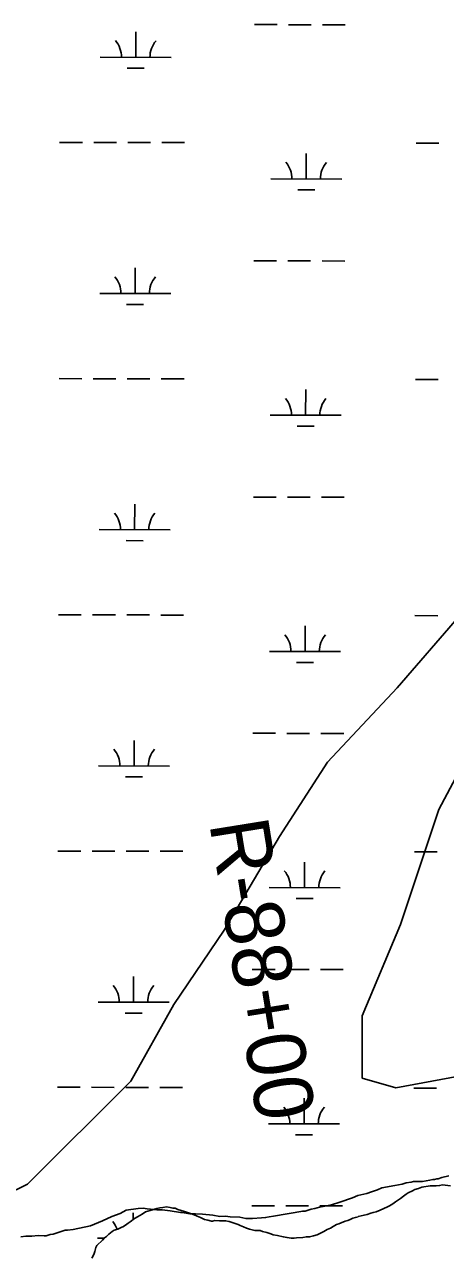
# Model space of a CAD drawing. Extents: x 3180038 to 3217926, y 922069 to 947485.
# Drawn here: x 3190976 to 3191568, y 934089 to 935823 of the extents above; entities that cross this region are included whole.
import ezdxf

# ---------------------------------------------------------------- set-up
doc = ezdxf.new("R2010")
doc.units = 0
for name, color, linetype in [('V-RIVR-RANG-IDEN', 7, 'Continuous'), ('V-SITE-VEGE', 7, 'Continuous'), ('V-TOPO-SHOR', 7, 'Continuous'), ('V-WETL-SWMP', 7, 'Continuous')]:
    doc.layers.add(name, color=color, linetype=linetype)

msp = doc.modelspace()

# ---------------------------------------------------------------- linework, layer by layer
at = {"layer": 'V-SITE-VEGE'}
for points in [[(3191573.2, 934201.6), (3191563.1, 934198.9), (3191558.1, 934197.2), (3191556.4, 934197.2), (3191553, 934196.3), (3191550.5, 934196.2), (3191546.2, 934195.3), (3191536.1, 934193.5), (3191523.4, 934193.4), (3191520.1, 934192.5), (3191513.3, 934191.6), (3191507.4, 934189.8), (3191497.3, 934188), (3191478.7, 934184.4), (3191472.9, 934181.8), (3191464.4, 934179.1), (3191457.7, 934176.5), (3191445.1, 934173.8), (3191437.5, 934170.3), (3191419.8, 934164.2), (3191408, 934160.7), (3191396.2, 934158), (3191391.1, 934157.1), (3191384.4, 934155.3), (3191379.3, 934154.4), (3191370.9, 934151.7), (3191367.5, 934151.7), (3191326.2, 934144.4), (3191320.3, 934143.5), (3191315.2, 934142.6), (3191309.3, 934142.5), (3191296.6, 934141.5), (3191287.3, 934141.4), (3191278.9, 934143), (3191265.3, 934143.7), (3191258.6, 934144.4), (3191250.9, 934144.3), (3191240.8, 934145.9), (3191226.4, 934147.4), (3191216.2, 934148.1), (3191208.6, 934148), (3191197.6, 934149.6), (3191195.1, 934149.6), (3191180.7, 934151.9), (3191169.7, 934153.5), (3191162.1, 934153.4), (3191148.5, 934154.9), (3191142.6, 934155.7), (3191135.8, 934155.6), (3191118.9, 934152.9), (3191110.5, 934148.5), (3191098.8, 934144.1), (3191085.3, 934138.1), (3191068.5, 934131.1), (3191044, 934125.7), (3191036.4, 934124.8)], [(3191036.4, 934124.8), (3191033, 934124.7), (3191016.2, 934119.4), (3191012, 934118.6), (3191006.1, 934116.8), (3191003.5, 934116.8), (3190995.1, 934117.5), (3190985.8, 934116.5), (3190977.3, 934116.4), (3190970.6, 934115.5)]]:
    msp.add_lwpolyline(points, dxfattribs=at)
at = {"layer": 'V-TOPO-SHOR'}
for points in [[(3190821.2, 934111.9), (3190980, 934189.6), (3191125.3, 934334.8), (3191186.1, 934442.9), (3191257, 934547.6), (3191334.7, 934679.4), (3191402.3, 934784.1), (3191500.2, 934888.8), (3191588, 934990.1), (3191682.6, 935040.8), (3191804.2, 935067.8), (3191908.9, 935037.4), (3192023.8, 934993.5), (3192152.2, 934963.1), (3192240, 934966.5), (3192290.7, 934983.4)], [(3191804.2, 935067.8), (3191674.2, 934933.6), (3191559.3, 934717.4), (3191505.3, 934555.2), (3191451.2, 934426.9), (3191451.2, 934339), (3191498.5, 934325.5), (3191680.9, 934359.3), (3191802.5, 934386.3), (3191957.9, 934440.4), (3192072.8, 934541.7), (3192147.1, 934764.7), (3192194.4, 934866), (3192240, 934966.5)]]:
    msp.add_lwpolyline(points, dxfattribs=at)
at = {"layer": 'V-WETL-SWMP'}
for p, q in [((3191132.2, 935776.7), (3191132.3, 935812.7)), ((3191299.4, 935822.7), (3191331.4, 935822.7)), ((3191347.4, 935822.6), (3191379.4, 935822.6)), ((3191395.4, 935822.5), (3191427.4, 935822.5)), ((3191082.2, 935776.8), (3191182.2, 935776.6)), ((3191120.2, 935761.3), (3191144.2, 935761.2)), ((3191025.1, 935656.9), (3191057.1, 935656.8)), ((3191073.1, 935656.8), (3191105.1, 935656.7)), ((3191121.1, 935656.7), (3191153.1, 935656.6)), ((3191169.1, 935656.5), (3191201.1, 935656.5)), ((3191527, 935655.7), (3191559, 935655.7)), ((3191372.3, 935605.3), (3191372.4, 935641.3)), ((3191322.3, 935605.5), (3191422.3, 935605.2)), ((3191360.3, 935589.9), (3191384.3, 935589.9)), ((3191131.5, 935444), (3191131.5, 935480)), ((3191298.6, 935490.1), (3191330.6, 935490)), ((3191346.6, 935490), (3191378.6, 935489.9)), ((3191394.6, 935489.9), (3191426.6, 935489.8)), ((3191081.5, 935444.1), (3191181.5, 935443.9)), ((3191119.4, 935428.6), (3191143.4, 935428.6)), ((3191024.3, 935324.2), (3191056.3, 935324.1)), ((3191072.3, 935324.1), (3191104.3, 935324)), ((3191120.3, 935324), (3191152.3, 935323.9)), ((3191168.3, 935323.9), (3191200.3, 935323.8)), ((3191526.2, 935323.1), (3191558.2, 935323)), ((3191371.5, 935272.7), (3191371.6, 935308.7)), ((3191321.5, 935272.8), (3191421.5, 935272.6)), ((3191359.5, 935257.3), (3191383.5, 935257.2)), ((3191130.7, 935111.4), (3191130.8, 935147.4)), ((3191297.9, 935157.4), (3191329.9, 935157.3)), ((3191345.9, 935157.3), (3191377.9, 935157.2)), ((3191393.9, 935157.2), (3191425.9, 935157.1)), ((3191080.7, 935111.5), (3191180.7, 935111.3)), ((3191118.7, 935096), (3191142.7, 935095.9)), ((3191023.6, 934991.5), (3191055.6, 934991.5)), ((3191071.6, 934991.4), (3191103.6, 934991.4)), ((3191119.6, 934991.3), (3191151.6, 934991.3)), ((3191167.6, 934991.2), (3191199.6, 934991.1)), ((3191370.8, 934940), (3191370.9, 934976)), ((3191525.5, 934990.4), (3191557.5, 934990.3)), ((3191320.8, 934940.1), (3191420.8, 934939.9)), ((3191358.7, 934924.6), (3191382.7, 934924.6)), ((3191297.1, 934824.8), (3191329.1, 934824.7)), ((3191345.1, 934824.6), (3191377.1, 934824.6)), ((3191393.1, 934824.5), (3191425.1, 934824.5)), ((3191129.9, 934778.7), (3191130, 934814.7)), ((3191079.9, 934778.8), (3191179.9, 934778.6)), ((3191117.9, 934763.3), (3191141.9, 934763.2)), ((3191022.8, 934658.9), (3191054.8, 934658.8)), ((3191070.8, 934658.8), (3191102.8, 934658.7)), ((3191118.8, 934658.7), (3191150.8, 934658.6)), ((3191166.8, 934658.6), (3191198.8, 934658.5)), ((3191524.7, 934657.7), (3191556.7, 934657.7)), ((3191370, 934607.4), (3191370.1, 934643.4)), ((3191320, 934607.5), (3191420, 934607.2)), ((3191358, 934592), (3191382, 934591.9)), ((3191296.4, 934492.1), (3191328.4, 934492)), ((3191344.4, 934492), (3191376.4, 934491.9)), ((3191392.4, 934491.9), (3191424.4, 934491.8)), ((3191129.2, 934446), (3191129.3, 934482)), ((3191079.2, 934446.2), (3191179.2, 934445.9)), ((3191117.2, 934430.6), (3191141.2, 934430.6)), ((3191022.1, 934326.2), (3191054.1, 934326.1)), ((3191070.1, 934326.1), (3191102.1, 934326)), ((3191118.1, 934326), (3191150.1, 934325.9)), ((3191166.1, 934325.9), (3191198.1, 934325.8)), ((3191524, 934325.1), (3191556, 934325)), ((3191369.3, 934274.7), (3191369.4, 934310.7)), ((3191319.3, 934274.8), (3191419.3, 934274.6)), ((3191357.2, 934259.3), (3191381.2, 934259.2)), ((3191295.6, 934159.4), (3191327.6, 934159.4)), ((3191343.6, 934159.3), (3191375.6, 934159.3)), ((3191391.6, 934159.2), (3191423.6, 934159.1)), ((3191128.5, 934139.9), (3191128.5, 934149.4)), ((3191078.4, 934113.5), (3191087.8, 934113.5))]:
    msp.add_line(p, q, dxfattribs=at)
for points in [[(3191575.4, 934187.5), (3191568.1, 934188.3), (3191564.1, 934188.6), (3191560.1, 934187.8), (3191555.3, 934187.3), (3191551.2, 934187.2), (3191546.8, 934187.2), (3191535.1, 934185.4), (3191530.3, 934183.8), (3191525.1, 934182.1), (3191521.9, 934180.4), (3191515.9, 934177.5), (3191513.1, 934175.5), (3191509.1, 934172.6), (3191505.1, 934169.3), (3191497.9, 934164.8), (3191494.3, 934161.9), (3191489.5, 934159.1), (3191486.7, 934157.8), (3191481.5, 934155.3), (3191476.7, 934153.3), (3191471, 934150.8), (3191466.6, 934149.9), (3191463.4, 934148.7), (3191458.2, 934147), (3191453.8, 934146.1), (3191449.7, 934144.9), (3191445.7, 934144), (3191445.3, 934143.6), (3191441.7, 934142.8), (3191438.1, 934141.9), (3191434.1, 934139.8), (3191430.9, 934138.6), (3191427.3, 934137.7), (3191421.6, 934135.2), (3191418.4, 934133.6), (3191415.2, 934132.7), (3191410.4, 934129.9), (3191406.4, 934127.8), (3191402, 934125.7), (3191397.2, 934122.8), (3191392.4, 934120.8), (3191387.6, 934118.3), (3191382.4, 934117), (3191377.1, 934115.3), (3191372.7, 934115.7), (3191367.5, 934114.8), (3191358.6, 934113.9), (3191355.4, 934113.5), (3191351, 934113.8), (3191345.3, 934114.5), (3191340, 934115.7), (3191332, 934117.2), (3191325.9, 934118.3), (3191322.3, 934119.9), (3191317, 934121.5), (3191310.9, 934123), (3191307.7, 934124.2), (3191303.7, 934124.5), (3191300, 934124.5), (3191292.3, 934126.4), (3191288.3, 934127.9), (3191283.8, 934129.5), (3191279.4, 934131.5), (3191276.5, 934133), (3191272.5, 934134.2), (3191264, 934136.9), (3191258.7, 934138.1), (3191255.5, 934138), (3191250.3, 934138), (3191243.8, 934138.3), (3191240.2, 934137.8), (3191239, 934137.8), (3191233.7, 934139), (3191229.3, 934140.1), (3191223.6, 934142.9), (3191218.7, 934144.4), (3191214.7, 934146.4), (3191210.6, 934148), (3191205.4, 934149.9), (3191200.9, 934151.1), (3191191.6, 934154.2)], [(3191191.6, 934154.2), (3191187.6, 934155.7), (3191184.3, 934156.1), (3191180.7, 934156.9), (3191175.4, 934157.6), (3191170.2, 934156.7), (3191166.2, 934156.3), (3191162.2, 934155.4), (3191157.3, 934154.1), (3191152.5, 934152.5), (3191146.1, 934150.8), (3191141.3, 934147.5), (3191138.1, 934145.4), (3191134.9, 934143.8), (3191130.5, 934141.3), (3191124.5, 934136.8), (3191121.7, 934134.8), (3191117.7, 934131.9), (3191114.1, 934129.4), (3191112.5, 934129), (3191106.9, 934126.5), (3191101.7, 934124.8), (3191098.9, 934122.8), (3191094.5, 934119.5), (3191091.3, 934116.2), (3191088.5, 934114.2), (3191085.7, 934110.9), (3191077.3, 934103.2), (3191076.2, 934100.3), (3191074.6, 934094.7), (3191073.5, 934090.6), (3191070.3, 934085.3)]]:
    msp.add_lwpolyline(points, dxfattribs=at)
for centre, start, end in [((3191077, 935777.3), 359.099, 40.6427), ((3191187.5, 935777), 139.099, 180.6426), ((3191317.1, 935605.9), 359.099, 40.6427), ((3191427.5, 935605.7), 139.099, 180.6426), ((3191076.2, 935444.6), 359.099, 40.6427), ((3191186.7, 935444.4), 139.099, 180.6426), ((3191316.3, 935273.3), 359.099, 40.6427), ((3191426.8, 935273), 139.099, 180.6426), ((3191075.5, 935112), 359.099, 40.6427), ((3191185.9, 935111.7), 139.099, 180.6426), ((3191315.5, 934940.6), 359.099, 40.6427), ((3191426, 934940.4), 139.099, 180.6426), ((3191074.7, 934779.3), 359.099, 40.6427), ((3191185.2, 934779.1), 139.099, 180.6426), ((3191314.8, 934608), 359.099, 40.6427), ((3191425.3, 934607.7), 139.099, 180.6426), ((3191073.9, 934446.6), 359.099, 40.6427), ((3191184.4, 934446.4), 139.099, 180.6426), ((3191314, 934275.3), 359.099, 40.6427), ((3191424.5, 934275), 139.099, 180.6426), ((3191073.2, 934114), 20.6371, 40.6427)]:
    msp.add_arc(centre, 35.2, start, end, dxfattribs=at)

# ---------------------------------------------------------------- texts
at = {"layer": 'V-RIVR-RANG-IDEN'}
msp.add_text('R-88+00', height=83, rotation=279.1733, dxfattribs=at).set_placement((3191235.7, 934698))

doc.saveas('drawing.dxf')
